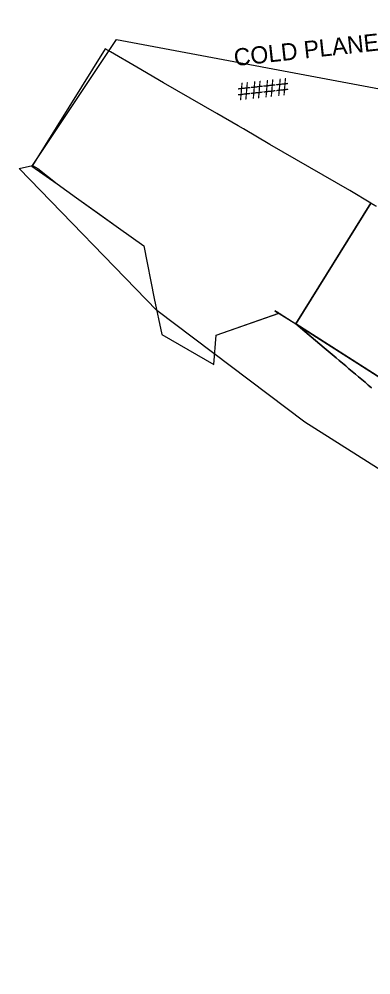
# Model space of a CAD drawing. Extents: x 1509538 to 1510847, y 401283 to 402022.
# Drawn here: x 1509538.4 to 1509595.6, y 401866.7 to 402022.2 of the extents above; entities that cross this region are included whole.
import ezdxf

# ---------------------------------------------------------------- set-up
doc = ezdxf.new("R2010")
doc.units = 0
for name, color, linetype in [('LAWE_P_T', 7, 'Continuous'), ('Level 1', 7, 'Continuous'), ('Level 2', 7, 'Continuous'), ('Level 24', 7, 'Continuous'), ('Level 3', 7, 'Continuous'), ('Level 5', 7, 'Continuous'), ('Level 8', 7, 'Continuous'), ('PCH_P', 7, 'Continuous')]:
    doc.layers.add(name, color=color, linetype=linetype)

msp = doc.modelspace()

# ---------------------------------------------------------------- linework, layer by layer
at = {"layer": 'Level 1'}
for p, q in [((1509552.36, 402017.38), (1509540.54, 401998.41)), ((1509552.36, 402017.38), (1509540.54, 401998.41)), ((1509583.4, 401972.64), (1509595.62, 401992.27)), ((1509583.4, 401972.64), (1509595.62, 401992.27))]:
    msp.add_line(p, q, dxfattribs=at)
for points in [[(1509595.62, 401992.27), (1509592.18, 401994.3), (1509587.85, 401996.81), (1509583.52, 401999.32), (1509579.19, 402001.83), (1509574.87, 402004.34), (1509574, 402004.84), (1509570.54, 402006.84), (1509566.21, 402009.35), (1509561.88, 402011.86), (1509557.55, 402014.37), (1509553.23, 402016.88), (1509552.36, 402017.38)], [(1509595.62, 401992.27), (1509592.18, 401994.3), (1509587.85, 401996.81), (1509583.52, 401999.32), (1509579.19, 402001.83), (1509574.87, 402004.34), (1509574, 402004.84), (1509570.54, 402006.84), (1509566.21, 402009.35), (1509561.88, 402011.86), (1509557.55, 402014.37), (1509553.23, 402016.88), (1509552.36, 402017.38)], [(1509540.54, 401998.41), (1509540.47, 401998.3), (1509544.55, 401995.39), (1509547.74, 401993.11), (1509551.08, 401990.72), (1509554.54, 401988.25), (1509558.65, 401985.31), (1509560.38, 401976.76), (1509561.58, 401970.87), (1509570.05, 401965.99), (1509570.42, 401970.76), (1509580.68, 401974.34), (1509583.4, 401972.64)], [(1509540.54, 401998.41), (1509541.4, 401997.9), (1509544.55, 401995.39), (1509547.74, 401993.11), (1509554.54, 401988.25), (1509558.65, 401985.31), (1509560.38, 401976.76), (1509561.58, 401970.87), (1509570.05, 401965.99), (1509570.42, 401970.76), (1509580.66, 401974.34), (1509580.01, 401974.76), (1509583.4, 401972.64)]]:
    msp.add_lwpolyline(points, dxfattribs=at)
at = {"layer": 'Level 2'}
for p, q in [((1509595.62, 401992.27), (1509583.4, 401972.64)), ((1509595.62, 401992.27), (1509583.4, 401972.64)), ((1509595.62, 401992.26), (1509595.62, 401992.27)), ((1509596.48, 401991.75), (1509595.62, 401992.27)), ((1509583.4, 401972.64), (1509623.48, 401946.99)), ((1509583.4, 401972.64), (1509584.24, 401972.1)), ((1509584.24, 401972.1), (1509623.48, 401946.99))]:
    msp.add_line(p, q, dxfattribs=at)
at = {"layer": 'Level 24'}
msp.add_lwpolyline([(1509697.15, 401864.06), (1509686.29, 401879.63), (1509675.11, 401894.56), (1509657.75, 401913.27), (1509630.7, 401928.99), (1509603.66, 401944.71), (1509584.86, 401956.59), (1509560.78, 401974.8), (1509538.38, 401997.91), (1509540.54, 401998.4), (1509554.21, 402018.88), (1509601.36, 402010.05), (1509610.5, 402004.57), (1509626.83, 401997.75), (1509642.89, 401994.81), (1509700.83, 401983.19), (1509716.67, 401971.54), (1509714.74, 401967.81), (1509741.2, 401959.3), (1509785.47, 401862.6)], dxfattribs=at)
at = {"layer": 'Level 3'}
msp.add_line((1509623.48, 401946.99), (1509583.4, 401972.64), dxfattribs=at)
for points in [[(1509583.4, 401972.64), (1509583.4, 401972.64)], [(1509583.4, 401972.64), (1509584.17, 401971.99), (1509588.03, 401968.73), (1509589.96, 401967.09), (1509590.48, 401966.65), (1509591, 401966.21), (1509591.53, 401965.76), (1509591.89, 401965.46), (1509592.05, 401965.32), (1509592.58, 401964.87), (1509593.1, 401964.43), (1509593.63, 401963.99), (1509594.15, 401963.54), (1509594.67, 401963.1), (1509595.2, 401962.66), (1509595.72, 401962.21)]]:
    msp.add_lwpolyline(points, dxfattribs=at)
at = {"layer": 'Level 5'}
for p, q in [((1509583.4, 401972.64), (1509595.62, 401992.27)), ((1509595.62, 401992.27), (1509583.4, 401972.64)), ((1509583.4, 401972.64), (1509595.62, 401992.27)), ((1509595.62, 401992.27), (1509583.4, 401972.64))]:
    msp.add_line(p, q, dxfattribs=at)
for points in [[(1509595.72, 401962.21), (1509595.2, 401962.66), (1509594.67, 401963.1), (1509594.15, 401963.54), (1509593.63, 401963.99), (1509593.1, 401964.43), (1509592.58, 401964.87), (1509592.05, 401965.32), (1509591.89, 401965.46), (1509591.53, 401965.76), (1509591, 401966.21), (1509590.48, 401966.65), (1509589.96, 401967.09), (1509588.03, 401968.73), (1509583.4, 401972.64)], [(1509583.4, 401972.64), (1509588.03, 401968.73), (1509589.96, 401967.09), (1509590.48, 401966.65), (1509591, 401966.21), (1509591.53, 401965.76), (1509591.89, 401965.46), (1509592.05, 401965.32), (1509592.58, 401964.87), (1509593.1, 401964.43), (1509593.63, 401963.99), (1509594.15, 401963.54), (1509594.67, 401963.1), (1509595.2, 401962.66), (1509595.72, 401962.21)]]:
    msp.add_lwpolyline(points, dxfattribs=at)
at = {"layer": 'Level 8'}
for p, q in [((1509583.4, 401972.64), (1509595.62, 401992.27)), ((1509595.62, 401992.27), (1509596.48, 401991.75)), ((1509584.24, 401972.1), (1509583.4, 401972.64)), ((1509623.48, 401946.99), (1509584.24, 401972.1))]:
    msp.add_line(p, q, dxfattribs=at)
at = {"layer": 'PCH_P'}
msp.add_line((1509595.62, 401992.27), (1509583.4, 401972.64), dxfattribs=at)

# ---------------------------------------------------------------- texts
at = {"layer": 'LAWE_P_T'}
for s, p in [('COLD PLANE#2 (OTHER)', (1509573.48, 402014.56)), ('####', (1509574.09, 402008.99))]:
    msp.add_text(s, height=2.8, rotation=6.2219, dxfattribs=at).set_placement(p)

doc.saveas('drawing.dxf')
